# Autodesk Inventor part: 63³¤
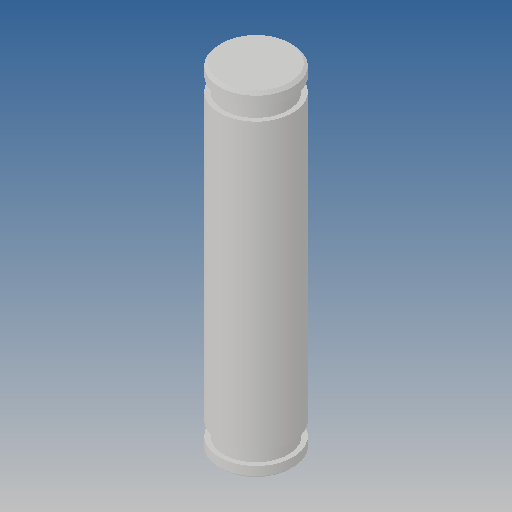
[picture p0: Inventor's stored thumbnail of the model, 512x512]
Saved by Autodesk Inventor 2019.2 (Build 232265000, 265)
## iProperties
Created: 2013-07
Part Number: 63³¤
Material: Ogólny
Document SubType Name: Modeling
Designer: CADENGINEERING4
Density: 1 g/cm^3
Appearance: Domyślna
Author: CADENGINEERING4
Revision Number: ÈÎºÎ
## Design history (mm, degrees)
feature "CALC-63³¤Ïú-1-solid1"
node "Bryła1"
